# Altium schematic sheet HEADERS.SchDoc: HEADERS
size A3; Author: Silvio Navaretti; CompanyName: Arduino srl; DocumentNumber: ABX00063; Revision: V1.2; SheetNumber: 2; SheetTotal: 8; RevAuthor: Silvio Navaretti
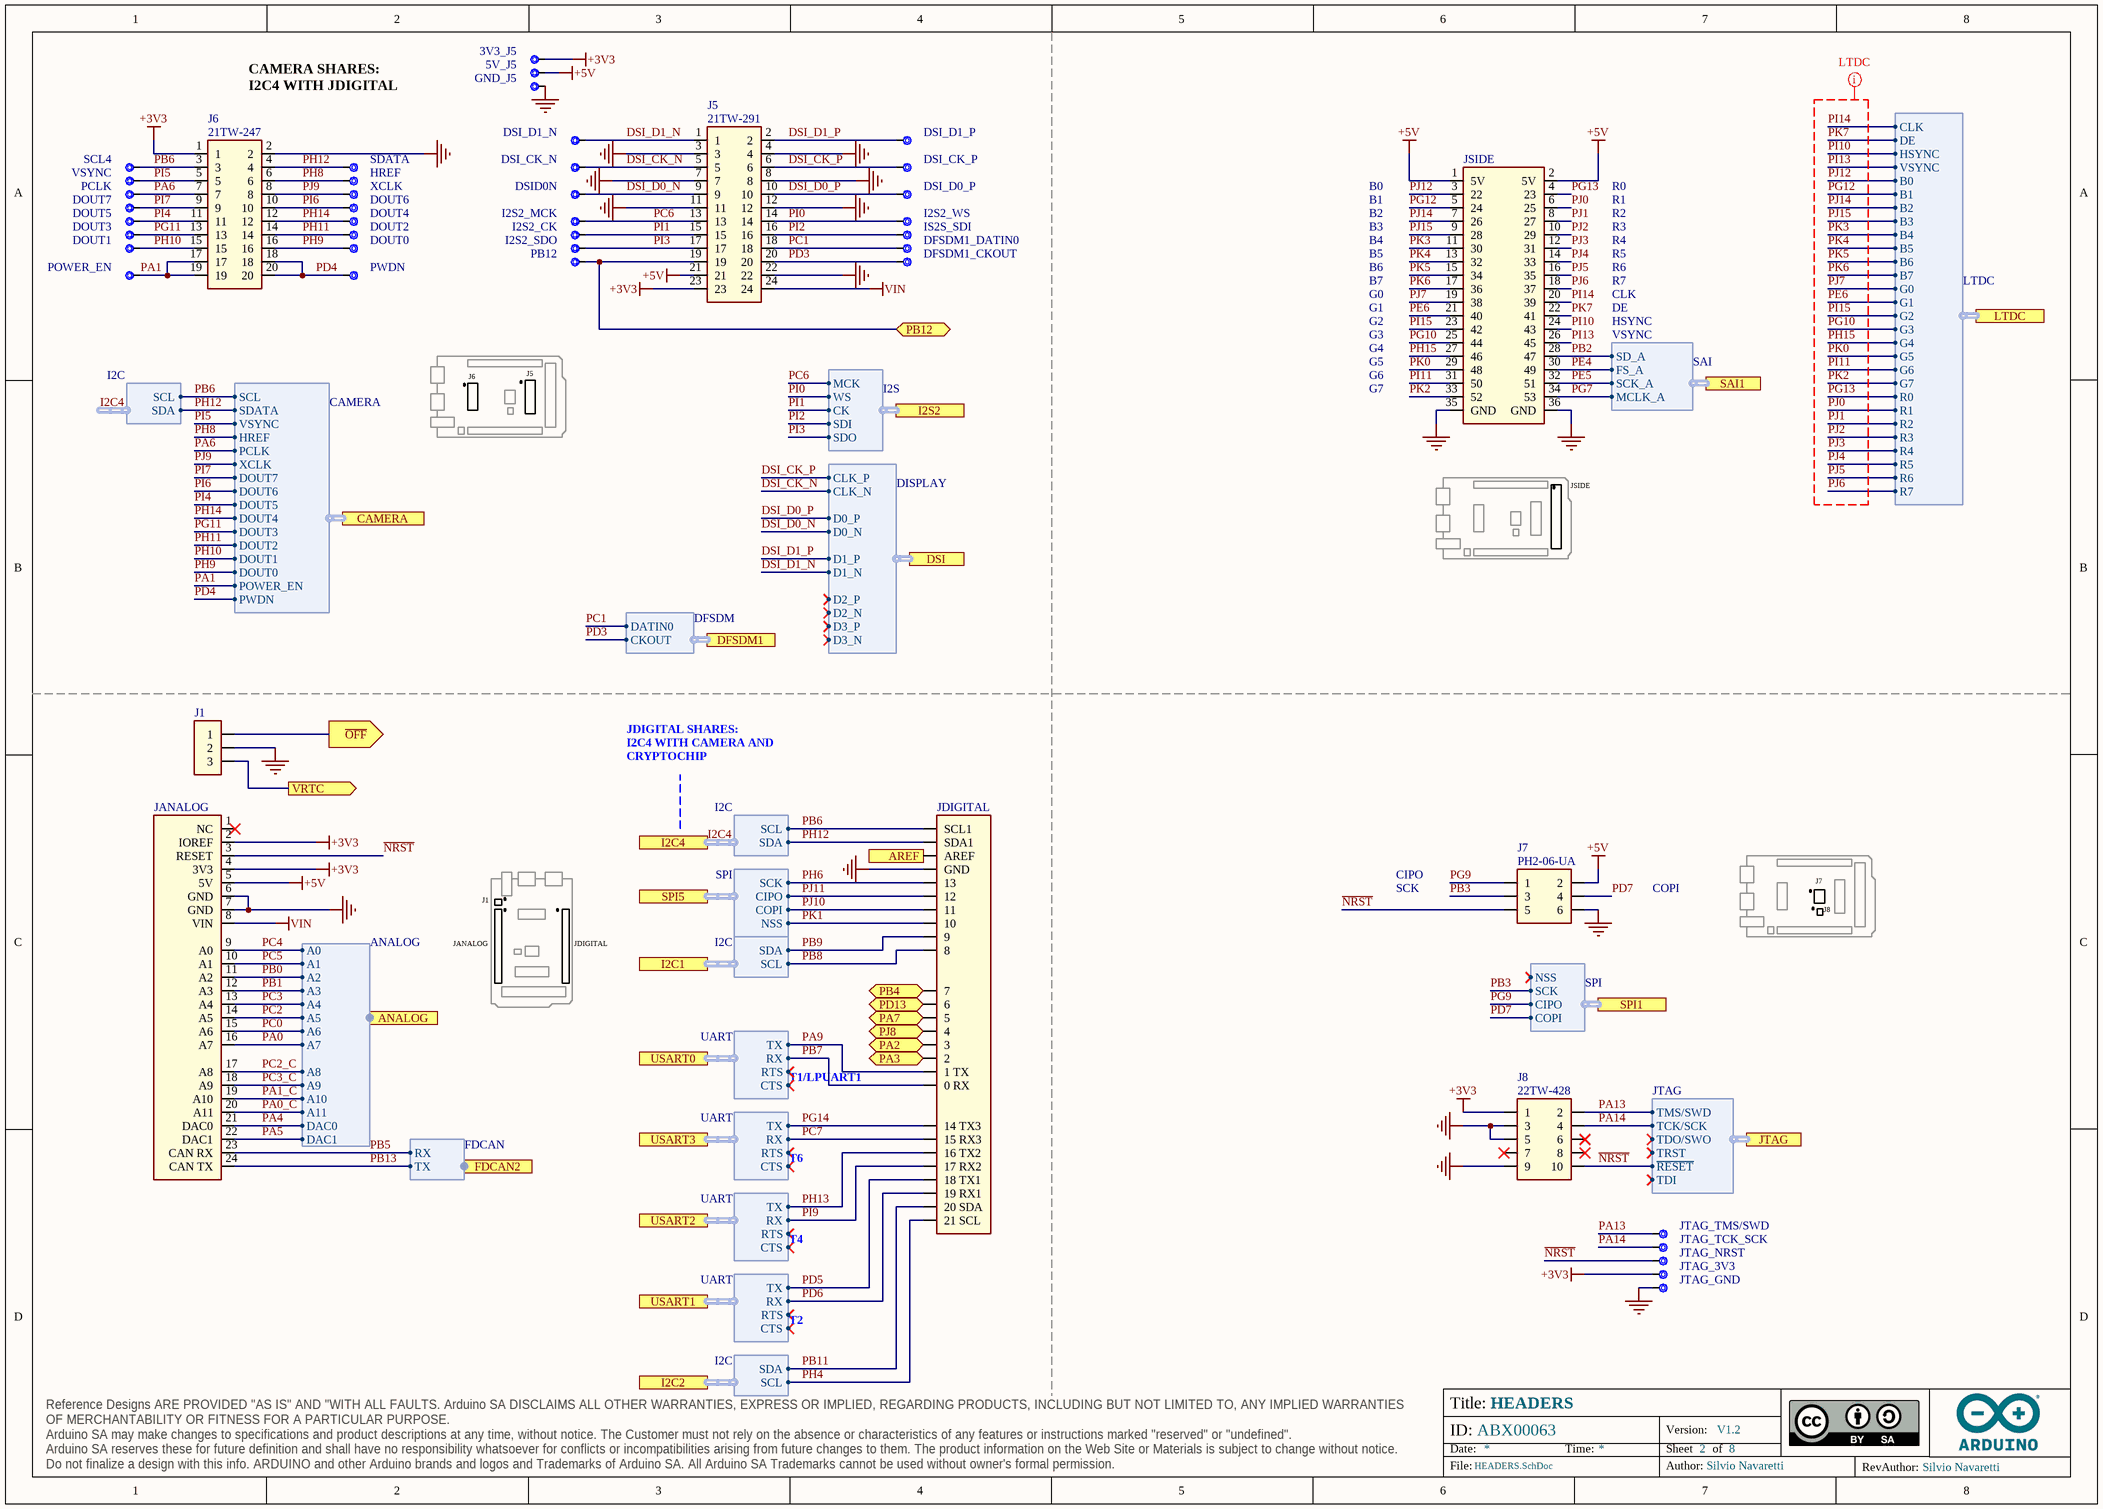
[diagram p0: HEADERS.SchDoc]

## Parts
3V3_J5  CMP-018-0005-A.3  [TP-1.00MM]  (value not drawn)  (no BOM)
5V_J5  CMP-018-0005-A.3  [TP-1.00MM]  (value not drawn)  (no BOM)
DFSDM1_CKOUT  CMP-018-0005-A.3  [TP-1.00MM]  (value not drawn)  (no BOM)
DFSDM1_DATIN0  CMP-018-0005-A.3  [TP-1.00MM]  (value not drawn)  (no BOM)
DOUT0  CMP-018-0005-A.3  [TP-1.00MM]  (value not drawn)  (no BOM)
DOUT1  CMP-018-0005-A.3  [TP-1.00MM]  (value not drawn)  (no BOM)
DOUT2  CMP-018-0005-A.3  [TP-1.00MM]  (value not drawn)  (no BOM)
DOUT3  CMP-018-0005-A.3  [TP-1.00MM]  (value not drawn)  (no BOM)
DOUT4  CMP-018-0005-A.3  [TP-1.00MM]  (value not drawn)  (no BOM)
DOUT5  CMP-018-0005-A.3  [TP-1.00MM]  (value not drawn)  (no BOM)
DOUT6  CMP-018-0005-A.3  [TP-1.00MM]  (value not drawn)  (no BOM)
DOUT7  CMP-018-0005-A.3  [TP-1.00MM]  (value not drawn)  (no BOM)
DSI_CK_N  CMP-018-0005-A.3  [TP-1.00MM]  (value not drawn)  (no BOM)
DSI_CK_P  CMP-018-0005-A.3  [TP-1.00MM]  (value not drawn)  (no BOM)
DSI_D0_P  CMP-018-0005-A.3  [TP-1.00MM]  (value not drawn)  (no BOM)
DSI_D1_N  CMP-018-0005-A.3  [TP-1.00MM]  (value not drawn)  (no BOM)
DSI_D1_P  CMP-018-0005-A.3  [TP-1.00MM]  (value not drawn)  (no BOM)
DSID0N  CMP-018-0005-A.3  [TP-1.00MM]  (value not drawn)  (no BOM)
GND_J5  CMP-018-0005-A.3  [TP-1.00MM]  (value not drawn)  (no BOM)
HREF  CMP-018-0005-A.3  [TP-1.00MM]  (value not drawn)  (no BOM)
I2S2_CK  CMP-018-0005-A.3  [TP-1.00MM]  (value not drawn)  (no BOM)
I2S2_MCK  CMP-018-0005-A.3  [TP-1.00MM]  (value not drawn)  (no BOM)
I2S2_SDO  CMP-018-0005-A.3  [TP-1.00MM]  (value not drawn)  (no BOM)
I2S2_WS  CMP-018-0005-A.3  [TP-1.00MM]  (value not drawn)  (no BOM)
IS2S_SDI  CMP-018-0005-A.3  [TP-1.00MM]  (value not drawn)  (no BOM)
J1  HEADER TH 2.54mm VERT. 1x003POS  [PIN HEADER 2.54mm VERT. 1x3POS]  (value not drawn)  (no BOM)
J5  21TW-291  [21TW-291]
J6  21TW-247  [21TW-247]
J7  PH2-06-UA  [2X03]
J8  22TW-428  [FTSH-105-01-F-DV-Footprint-1]
JANALOG  20TW-887  [GIGA header custom analog]  (value not drawn)
JDIGITAL  20TW-890  [GIGA Header custom digital]  (value not drawn)
JSIDE  20TW-891  [GIGA custom header side-Footprint-1]  (value not drawn)
JTAG_3V3  CMP-018-0005-A.3  [TP-1.00MM]  (value not drawn)  (no BOM)
JTAG_GND  CMP-018-0005-A.3  [TP-1.00MM]  (value not drawn)  (no BOM)
JTAG_NRST  CMP-018-0005-A.3  [TP-1.00MM]  (value not drawn)  (no BOM)
JTAG_TCK_SCK  CMP-018-0005-A.3  [TP-1.00MM]  (value not drawn)  (no BOM)
JTAG_TMS/SWD  CMP-018-0005-A.3  [TP-1.00MM]  (value not drawn)  (no BOM)
PB12  CMP-018-0005-A.3  [TP-1.00MM]  (value not drawn)  (no BOM)
PCLK  CMP-018-0005-A.3  [TP-1.00MM]  (value not drawn)  (no BOM)
POWER_EN  CMP-018-0005-A.3  [TP-1.00MM]  (value not drawn)  (no BOM)
PWDN  CMP-018-0005-A.3  [TP-1.00MM]  (value not drawn)  (no BOM)
SCL4  CMP-018-0005-A.3  [TP-1.00MM]  (value not drawn)  (no BOM)
SDATA  CMP-018-0005-A.3  [TP-1.00MM]  (value not drawn)  (no BOM)
VSYNC  CMP-018-0005-A.3  [TP-1.00MM]  (value not drawn)  (no BOM)
XCLK  CMP-018-0005-A.3  [TP-1.00MM]  (value not drawn)  (no BOM)

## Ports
ANALOG (harness ANALOG), AREF (out), CAMERA (harness CAMERA), DFSDM1 (harness DFSDM), DSI (harness DISPLAY), FDCAN2 (harness FDCAN), I2C1 (harness I2C), I2C2 (harness I2C), I2C4 (harness I2C), I2S2 (harness I2S), JTAG (harness JTAG), LTDC (harness LTDC), PA2 (bidir), PA3 (bidir), PA7 (bidir), PB4 (bidir), PB12 (bidir), PD13 (bidir), PJ8 (bidir), SAI1 (harness SAI), SPI1 (harness SPI), SPI5 (harness SPI), USART0 (harness UART), USART1 (harness UART), USART2 (harness UART), USART3 (harness UART), VRTC (out), ~{OFF} (out)

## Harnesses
SPI: NSS, SCK, CIPO, COPI
I2C: SDA, SCL
LTDC: B0, B1, B2, B3, B4, B5, B6, B7, CLK, DE, G0, G1, G2, G3, G4, G5, G6, G7, HSYNC, R0, R1, R2, R3, R4, R5, R6, R7, VSYNC
SAI: SD_A, FS_A, SCK_A, MCLK_A
ANALOG: A0, A1, A2, A3, A7, A6, A5, A4, A8, A9, A10, A11, DAC0, DAC1
I2S: CK, SDI, SDO, WS, MCK
DISPLAY: CLK_N, CLK_P, D0_N, D0_P, D1_N, D1_P, D2_N, D2_P, D3_N, D3_P
DFSDM: DATIN0, CKOUT
CAMERA: SCL, SDATA, VSYNC, HREF, PCLK, XCLK, DOUT7, DOUT6, DOUT5, DOUT4, DOUT3, DOUT2, DOUT1, DOUT0, POWER_EN, PWDN
JTAG: ~{RESET}, TCK/SCK, TDI, TDO/SWO, TMS/SWD, TRST
UART: RX, TX, RTS, CTS
FDCAN: RX, TX

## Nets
+3V3: 3V3_J5.X J5.23 J6.1 J8.1 JANALOG.2(IOREF) JANALOG.4(3V3) JTAG_3V3.X
+5V: 5V_J5.X J5.21 J7.2 JANALOG.5(5V) JSIDE.1(5V) JSIDE.2(5V)
GND: GND_J5.X J1.2 J5.3 J5.4 J5.7 J5.8 J5.11 J5.12 J5.22 J6.2 J7.6 J8.3 J8.5 J8.9 JANALOG.6(GND) JANALOG.7(GND) JDIGITAL.4(GND) JSIDE.35(GND) JSIDE.36(GND) JTAG_GND.X
VIN: J5.24 JANALOG.8(VIN)
AREF: JDIGITAL.3(AREF) ; port AREF
DSI_CK_N: DSI_CK_N.X J5.5 ; port DSI.CLK_N
DSI_CK_P: DSI_CK_P.X J5.6 ; port DSI.CLK_P
DSI_D0_N: DSID0N.X J5.9 ; port DSI.D0_N
DSI_D0_P: DSI_D0_P.X J5.10 ; port DSI.D0_P
DSI_D1_N: DSI_D1_N.X J5.1 ; port DSI.D1_N
DSI_D1_P: DSI_D1_P.X J5.2 ; port DSI.D1_P
~{NRST}: J7.5 J8.10 JANALOG.3(RESET) JTAG_NRST.X ; port JTAG.~{RESET}
~{OFF}: J1.1 ; port ~{OFF}
PA0: JANALOG.16(A7) ; port ANALOG.A7
PA0_C: JANALOG.20(A11) ; port ANALOG.A11
PA1: J6.17 J6.19 POWER_EN.X ; port CAMERA.POWER_EN
PA1_C: JANALOG.19(A10) ; port ANALOG.A10
PA2: JDIGITAL.15(3) ; port PA2
PA3: JDIGITAL.16(2) ; port PA3
PA4: JANALOG.21(DAC0) ; port ANALOG.DAC0
PA5: JANALOG.22(DAC1) ; port ANALOG.DAC1
PA6: J6.7 PCLK.X ; port CAMERA.PCLK
PA7: JDIGITAL.13(5) ; port PA7
PA9: JDIGITAL.17(1_TX) ; port USART0.TX
PA13: J8.2 JTAG_TMS/SWD.X ; port JTAG.TMS/SWD
PA14: J8.4 JTAG_TCK_SCK.X ; port JTAG.TCK/SCK
PB0: JANALOG.11(A2) ; port ANALOG.A2
PB1: JANALOG.12(A3) ; port ANALOG.A3
PB2: JSIDE.28(47) ; port SAI1.SD_A
PB3: J7.3 ; port SPI1.SCK
PB4: JDIGITAL.11(7) ; port PB4
PB5: JANALOG.23(CAN_RX) ; port FDCAN2.RX
PB6: J6.3 JDIGITAL.1(SCL1) SCL4.X ; port CAMERA.SCL, port I2C4.SCL  [project net I2C4.SCL]
PB7: JDIGITAL.18(0_RX) ; port USART0.RX
PB8: JDIGITAL.10(8) ; port I2C1.SCL
PB9: JDIGITAL.9 ; port I2C1.SDA
PB11: JDIGITAL.25(20_SDA) ; port I2C2.SDA
PB12: J5.19 PB12.X ; port PB12
PB13: JANALOG.24(CAN_TX) ; port FDCAN2.TX
PC0: JANALOG.15(A6) ; port ANALOG.A6
PC1: DFSDM1_DATIN0.X J5.18 ; port DFSDM1.DATIN0
PC2: JANALOG.14(A5) ; port ANALOG.A5
PC2_C: JANALOG.17(A8) ; port ANALOG.A8
PC3: JANALOG.13(A4) ; port ANALOG.A4
PC3_C: JANALOG.18(A9) ; port ANALOG.A9
PC4: JANALOG.9(A0) ; port ANALOG.A0
PC5: JANALOG.10(A1) ; port ANALOG.A1
PC6: I2S2_MCK.X J5.13 ; port I2S2.MCK
PC7: JDIGITAL.20(15_RX3) ; port USART3.RX
PD3: DFSDM1_CKOUT.X J5.20 ; port DFSDM1.CKOUT
PD4: J6.18 J6.20 PWDN.X ; port CAMERA.PWDN
PD5: JDIGITAL.23(18_TX1) ; port USART1.TX
PD6: JDIGITAL.24(19_RX1) ; port USART1.RX
PD7: J7.4 ; port SPI1.COPI
PD13: JDIGITAL.12(6) ; port PD13
PE4: JSIDE.30(49) ; port SAI1.FS_A
PE5: JSIDE.32(51) ; port SAI1.SCK_A
PE6: JSIDE.21(40) ; port LTDC.G1
PG7: JSIDE.34(53) ; port SAI1.MCLK_A
PG9: J7.1 ; port SPI1.CIPO
PG10: JSIDE.25(44) ; port LTDC.G3
PG11: DOUT3.X J6.13 ; port CAMERA.DOUT3
PG12: JSIDE.5(24) ; port LTDC.B1
PG13: JSIDE.4(23) ; port LTDC.R0
PG14: JDIGITAL.19(14_TX3) ; port USART3.TX
PH4: JDIGITAL.26(21_SCL) ; port I2C2.SCL
PH6: JDIGITAL.5(13) ; port SPI5.SCK
PH8: HREF.X J6.6 ; port CAMERA.HREF
PH9: DOUT0.X J6.16 ; port CAMERA.DOUT0
PH10: DOUT1.X J6.15 ; port CAMERA.DOUT1
PH11: DOUT2.X J6.14 ; port CAMERA.DOUT2
PH12: J6.4 JDIGITAL.2(SDA1) SDATA.X ; port CAMERA.SDATA, port I2C4.SDA  [project net I2C4.SDA]
PH13: JDIGITAL.21(16_TX2) ; port USART2.TX
PH14: DOUT4.X J6.12 ; port CAMERA.DOUT4
PH15: JSIDE.27(46) ; port LTDC.G4
PI0: I2S2_WS.X J5.14 ; port I2S2.WS
PI1: I2S2_CK.X J5.15 ; port I2S2.CK
PI2: IS2S_SDI.X J5.16 ; port I2S2.SDI
PI3: I2S2_SDO.X J5.17 ; port I2S2.SDO
PI4: DOUT5.X J6.11 ; port CAMERA.DOUT5
PI5: J6.5 VSYNC.X ; port CAMERA.VSYNC
PI6: DOUT6.X J6.10 ; port CAMERA.DOUT6
PI7: DOUT7.X J6.9 ; port CAMERA.DOUT7
PI9: JDIGITAL.22(17_RX2) ; port USART2.RX
PI10: JSIDE.24(43) ; port LTDC.HSYNC
PI11: JSIDE.31(50) ; port LTDC.G6
PI13: JSIDE.26(45) ; port LTDC.VSYNC
PI14: JSIDE.20(39) ; port LTDC.CLK
PI15: JSIDE.23(42) ; port LTDC.G2
PJ0: JSIDE.6(25) ; port LTDC.R1
PJ1: JSIDE.8(27) ; port LTDC.R2
PJ2: JSIDE.10(29) ; port LTDC.R3
PJ3: JSIDE.12(31) ; port LTDC.R4
PJ4: JSIDE.14(33) ; port LTDC.R5
PJ5: JSIDE.16(35) ; port LTDC.R6
PJ6: JSIDE.18(37) ; port LTDC.R7
PJ7: JSIDE.19(38) ; port LTDC.G0
PJ8: JDIGITAL.14(4) ; port PJ8
PJ9: J6.8 XCLK.X ; port CAMERA.XCLK
PJ10: JDIGITAL.7(11) ; port SPI5.COPI
PJ11: JDIGITAL.6(12) ; port SPI5.CIPO
PJ12: JSIDE.3(22) ; port LTDC.B0
PJ14: JSIDE.7(26) ; port LTDC.B2
PJ15: JSIDE.9(28) ; port LTDC.B3
PK0: JSIDE.29(48) ; port LTDC.G5
PK1: JDIGITAL.8(10) ; port SPI5.NSS
PK2: JSIDE.33(52) ; port LTDC.G7
PK3: JSIDE.11(30) ; port LTDC.B4
PK4: JSIDE.13(32) ; port LTDC.B5
PK5: JSIDE.15(34) ; port LTDC.B6
PK6: JSIDE.17(36) ; port LTDC.B7
PK7: JSIDE.22(41) ; port LTDC.DE
VRTC: J1.3 ; port VRTC

Not connected (* = marked no-connect by the designer): J8 6* 7* 8*; JANALOG 1(NC)*

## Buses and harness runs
harness I2C4 = port I2C4

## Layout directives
net class LTDC: PE6, PG10, PG12, PG13, PH15, PI10, PI11, PI13, PI14, PI15, PJ0, PJ1, PJ2, PJ3, PJ4, PJ5, PJ6, PJ7, PJ12, PJ14, PJ15, PK0, PK2, PK3, PK4, PK5, PK6, PK7

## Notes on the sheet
- CAMERA SHARES:
  I2C4 WITH JDIGITAL
- B0
- B1
- B2
- B3
- B4
- R0
- R1
- R2
- R3
- R4
- B5
- B6
- B7
- G0
- G1
- R5
- R6
- R7
- CLK
- DE
- J6
- J5
- G2
- G3
- G4
- G5
- G6
- HSYNC
- VSYNC
- G7
- JSIDE
- JDIGITAL SHARES:
  I2C4 WITH CAMERA AND CRYPTOCHIP
- J1
- CIPO
- SCK
- COPI
- J7
- J8
- JANALOG
- JDIGITAL
- H7: USART1/LPUART1
- H7: USART6
- H7: USART4
- H7: USART2

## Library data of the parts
3V3_J5 5V_J5 DFSDM1_CKOUT DFSDM1_DATIN0 DOUT0-DOUT7 DSI_CK_N DSI_CK_P DSI_D0_P DSI_D1_N DSI_D1_P DSID0N GND_J5 HREF I2S2_CK I2S2_MCK I2S2_SDO I2S2_WS IS2S_SDI JTAG_3V3 JTAG_GND JTAG_NRST JTAG_TCK_SCK JTAG_TMS/SWD PB12 PCLK POWER_EN PWDN SCL4 SDATA VSYNC XCLK = UT0013-A.4: Test point 1.00mm
J1 = J0237-A.2: MOUNT A MALE HEADER TH 2.54mm VERT. 1x003POS; Code Arduino: J0237
J5 = J0265-A.9: CONN SOCKET 2ROW 24POS VERTICAL PASS THROUGH + SMD with fixing + reel + cap for pick and place; Manufacturer: 4UCON; Connector Type: BOARD CONNECTOR; Code Arduino: J0265; Number of Contacts: 24
J6 = J0249-A.9: CONN SOCKET 2ROW 20POS VERTICAL PASS THROUGH + SMD with fixing + pick and place cap, in reel; Manufacturer: 4UCON; Connector Type: BOARD CONNECTOR; Code Arduino: J0249; Number of Contacts: 20
J7 = J0004-A.4: CONN Header Through Hole 6 position 0.100" (2.54mm); Manufacturer: Adam Tech; Code Arduino: 0114
J8 = J0089-A.10: CONN HEADER SMD 10POS 2x5 1.27MM JTAG reel, capsfor pick and place; Manufacturer: 4UCON; Code Arduino: J0089; Gender: Male; Current Rating: 1.75A; Connector Type: Male Pin
JANALOG = J0313-A.4: CONN THD 24X1 CUSTOM PITCH DUE JANALOG GREY; Manufacturer: 4UCON; Number of Contacts: 24; Code Arduino: 3654
JDIGITAL = J0262-A.9: CONN THD 1X26 CUSTOM PITCH DUE JDIGITAL GREY; Manufacturer: 4UCON; Code Arduino: 3653; Number of Positions: 26; Gender: F
JSIDE = J0315-A.3: CONN THD 18X2 36V DUE JSIDE CUSTOM GREY; Manufacturer: 4UCON; Number of Contacts: 36; Code Arduino: 3656; Gender: F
